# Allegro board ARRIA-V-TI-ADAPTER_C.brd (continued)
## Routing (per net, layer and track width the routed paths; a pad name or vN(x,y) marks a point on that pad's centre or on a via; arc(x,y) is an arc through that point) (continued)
N18163859: length 6.4
  TOP w0.165: v1(218.69,72.39) 219.27,72.96 J2.49
  BOTTOM w0.165: v1(218.69,72.39) R8.1
N18163866: length 7.3
  TOP w0.165: J2.55 221.58,71.46 v1(218.69,68.58)
  BOTTOM w0.165: v1(218.69,68.58) R12.1
N18163868: length 8
  TOP w0.165: J2.57 221.84,70.96 219.46,68.58 219.46,68.07 v1(218.69,67.31)
  BOTTOM w0.165: v1(218.69,67.31) R14.1
N18164112: length 12
  TOP w0.165: J2.38 v1(228.04,75.97)
  BOTTOM w0.165: v1(228.04,75.97) 218.39,75.97 218.16,76.2 R3.2
N18164130: length 12.1
  TOP w0.165: J2.40 v1(227.4,75.47)
  BOTTOM w0.165: v1(227.4,75.47) 226.47,75.47 225.93,74.93 R4.2
N18164140: length 12.6
  TOP w0.165: J2.50 v1(227.4,72.96)
  BOTTOM w0.165: v1(227.4,72.96) 222.44,72.96 220.6,71.12 R7.2
N18164142: length 13
  TOP w0.165: J2.52 v1(228.04,72.46)
  BOTTOM w0.165: R9.2 220.34,69.85 222.25,71.75 227.33,71.75 v1(228.04,72.46)
N18166476: length 12
  TOP w0.165: J2.48 v1(228.04,73.46)
  BOTTOM w0.165: R5.2 227.84,73.66 v1(228.04,73.46)
N18166670: length 13
  TOP w0.165: J2.26 v1(228.04,78.97)
  BOTTOM w0.165: v1(228.04,78.97) 228.04,79.45 227.63,79.86 219.3,79.86 218.19,78.74 R1.2
N18166673: length 13.3
  TOP w0.165: J2.28 v1(227.4,78.47)
  BOTTOM w0.165: v1(227.4,78.47) 227.4,78.95 226.99,79.36 220.05,79.36 218.16,77.47 R2.2

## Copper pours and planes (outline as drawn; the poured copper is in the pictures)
GND on TOP: 114.68,0.3 114.68,0.64 94.11,0.64 94.11,68.83 132.21,68.83 132.21,105.54 69.21,105.54 69.21,87.76 0.64,87.76 0.64,146.05 233.81,146.05 233.81,0.64 114.78,0.64 114.78,0.3 ; 1 cut-out
GND on BOTTOM: 94.11,0.91 94.11,68.83 132.21,68.83 132.21,105.54 69.21,105.54 69.21,87.76 0.69,87.76 0.69,146.05 233.81,146.05 233.81,0.91 ; 5 cut-outs
GND on LAYER2_GND1: 114.68,0 114.68,0.64 94.11,0.64 94.11,68.83 132.21,68.83 132.21,105.54 69.21,105.54 69.21,87.76 0.64,87.76 0.64,146.05 233.81,146.05 233.81,0.64 114.78,0.64 114.78,0
GND on LAYER3: 114.78,0.64 114.78,0.41 114.68,0.41 114.68,0.64 94.11,0.64 94.11,68.83 132.21,68.83 132.21,105.54 69.21,105.54 69.21,87.76 0.64,87.76 0.64,146.05 233.81,146.05 233.81,0.64 ; 11 cut-outs
GND on LAYER4_GND2: 94.11,0.76 94.11,68.83 132.21,68.83 132.21,105.54 69.21,105.54 69.21,87.76 0.64,87.76 0.64,146.05 233.81,146.05 233.81,0.76
GND on LAYER5_GND3: 114.68,0.38 114.68,0.64 94.11,0.64 94.11,68.83 132.21,68.83 132.21,105.54 69.21,105.54 69.21,87.76 0.64,87.76 0.64,146.05 233.81,146.05 233.81,0.64 114.78,0.64 114.78,0.38
GND on LAYER6: 114.68,0.41 114.68,0.64 94.11,0.64 94.11,68.83 132.21,68.83 132.21,105.54 69.21,105.54 69.21,87.76 0.64,87.76 0.64,146.05 233.81,146.05 233.81,0.64 114.78,0.64 114.78,0.41 ; 1 cut-out
GND on LAYER7_GND4: 94.11,0.91 94.11,68.83 132.21,68.83 132.21,105.54 69.21,105.54 69.21,87.76 0.69,87.76 0.69,146.05 233.81,146.05 233.81,0.91

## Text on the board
BOTTOM: LAYER 8 (BOTTOM SIDE)
Ref Des/Assembly Bottom: J1 | J4 | MATES WITH | ALTERA YHSMC | PORT B CONN J2 | TSW1266  EVM | 40 | 30 | 20 | 10 | 1 | J3 | ALTERA FMC | CONNECTOR J10 | J2 | 61 | 59 | 121 | 119 | 179 | 60 | 2 | 62 | 120 | 122 | 180 | A | B | C | D | E | F | G | H | J | K | BOTTOM SIDE
Board Geometry/Soldermask Bottom: SOLDERMASK BOTTOM
Ref Des/Silkscreen Bottom: ALTERA HSMC | PORT B CONN J2 | ALTERA | FMC CONN J10 | MATES WITH | TSW1266 EVM | SILKSCREEN BOTTOM
User.Comments: ARRIA V-TI ADAPTER | REV C | TEXAS INSTRUMENTS | ALL OUTER LAYERS USING A 6.5MIL TRACE WIDTH SHALL BE 50 OHMS +/- 10%. | ALL INNER LAYERS USING A 4.4MIL TRACE WIDTH AND 7.6MIL SPACING SHALL BE 100 OHMS DIFFERENTIAL +/- 10%.
TOP: LAYER 1 (TOP SIDE)
Ref Des/Assembly Top: 40 | 30 | 20 | 10 | 1 | 119 | 179 | 121 | 59 | 61 | 2 | 62 | 60 | 120 | 180 | 122 | J3 | TSW30SH84 EVM | MATES WITH | J1 | TOP SIDE
Board Geometry/Soldermask Top: SOLDERMASK TOP
Ref Des/Silkscreen Top: J4 | HSMC I/F | MADE IN USA | J3 | FMC I/F | TSW1266 I/F | J1 | TSW30SH84 I/F | SILKSCREEN TOP
LAYER2_GND1: LAYER 2 - GROUND PLANE
LAYER3: LAYER 3
LAYER4_GND2: LAYER 4 - GROUND PLANE
LAYER5_GND3: LAYER 5 - GROUND PLANE
LAYER6: LAYER 6
LAYER7_GND4: LAYER 7 - GROUND PLANE
DIMENSION: PASTEMASK TOP
PAGE_OUTLINE: PASTEMASK BOTTOM
User.10: 05-11-12
User.13: BOTTOM SIDE
User.27: A | B | C | D | E | F | G | H | J | K | ON | OFF | 6 | 4 | J7 | 3 | J10 | 1 | 2 | 39 | 40 | 42 | 99 | 100 | 102 | 101 | 160 | 159 | J4 | SW1 | D1
User.28: MOUNTED ON SECONDARY SIDE | PRIMARY | SIDE | MOUNTED ON
User.29: DC INPUT | 12V_ATX
User.30: A | B | C | D | E | F | G | H | J | K | 2 | 62 | 60 | 119 | 179 | 121 | 59 | 61 | 1 | J2 | R1 | R3 | R5 | R7 | R12 | R2 | R4 | R8 | R9 | R14 | TSW1266  EVM | MATES WITH | J1 | CONNECTOR J10 | ALTERA FMC | J3 | 40 | 30 | 20 | 10 | ALTERA YHSMC | PORT B CONN J2 | J4 | 180 | 122 | 120
User.32: FIGURE | SIZE | 10.0 | 106.0 | 156.0 | 40.0 | 50.0 | DRILL CHART: TOP to BOTTOM | ALL UNITS ARE IN MILS | PLATED | NON-PLATED | QTY | 1272 | 2 | 4 | 6
